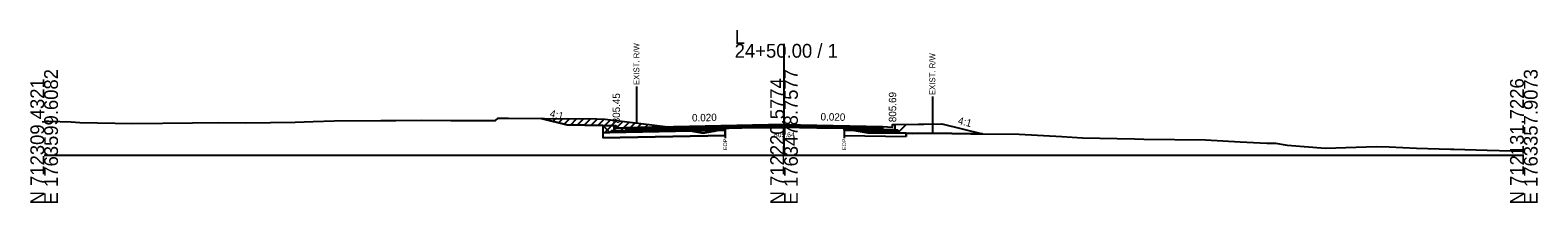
# Model space of a CAD drawing. Extents: x -26 to 5303, y -10 to 9578.
# Drawn here: x 997.2 to 1302.8, y 4490.3 to 4525.4 of the extents above; entities that cross this region are included whole.
import ezdxf

# ---------------------------------------------------------------- set-up
doc = ezdxf.new("R2010")
doc.units = 0
for name, color, linetype in [('Default', 7, 'Continuous'), ('Exist CMT Pavement', 7, 'Continuous'), ('Exist Cross Section Cell', 7, 'Continuous'), ('Exist XS Ground Line', 7, 'Continuous'), ('Old_Level_10', 7, 'Continuous'), ('Old_Level_3', 7, 'Continuous'), ('Prop CMT Conc Surface', 7, 'Continuous'), ('Prop CMT Concrete Structures', 7, 'Continuous'), ('Prop CMT Pvmt Course 1', 7, 'Continuous'), ('Prop CMT Pvmt Course 1 CG', 7, 'Continuous'), ('Prop CMT Pvmt Course 2', 7, 'Continuous'), ('Prop CMT Pvmt Course 3', 7, 'Continuous'), ('Prop CMT Pvmt Surface', 7, 'Continuous'), ('Prop CMT Slope Grass', 7, 'Continuous'), ('Prop CMT Subgrade Earthwork', 7, 'Continuous'), ('Prop Shade Light', 7, 'Continuous'), ('Prop XS Earthwork Shape', 7, 'Continuous'), ('Prop XS Hydro Elevations', 7, 'Continuous'), ('Prop XS SE Text', 7, 'Continuous'), ('Prop XS Side Slope Text', 7, 'Continuous'), ('Prop XS Wedging', 7, 'Continuous'), ('Scratch_Level_5', 7, 'Continuous')]:
    doc.layers.add(name, color=color, linetype=linetype)

msp = doc.modelspace()

# ---------------------------------------------------------------- linework, layer by layer
at = {"layer": 'Exist CMT Pavement'}
msp.add_lwpolyline([(1138.07, 4505.48), (1138.48, 4505.48), (1138.8, 4505.49), (1140.7, 4505.56), (1141.47, 4505.57), (1143.8, 4505.6), (1144.64, 4505.61), (1145.95, 4505.61), (1146.91, 4505.62), (1147.74, 4505.63), (1148.86, 4505.64), (1149.6, 4505.64), (1150.38, 4505.65), (1150.92, 4505.65), (1151.31, 4505.65), (1153.11, 4505.62), (1154.89, 4505.6), (1156.22, 4505.58), (1156.68, 4505.57), (1157.31, 4505.56), (1158.47, 4505.54), (1159.32, 4505.53), (1160.25, 4505.53), (1160.8, 4505.52), (1162.19, 4505.49), (1162.19, 4505.49)], dxfattribs=at)
at = {"layer": 'Exist Cross Section Cell'}
for p, q in [((1150, 4500), (1150, 4522.59)), ((1000, 4500), (1150, 4500)), ((1150, 4500), (1300, 4500))]:
    msp.add_line(p, q, dxfattribs=at)
at = {"layer": 'Exist XS Ground Line'}
msp.add_lwpolyline([(1000, 4506.88), (1000.93, 4506.88), (1005.5, 4506.75), (1007.2, 4506.64), (1018, 4506.42), (1030.09, 4506.57), (1035.26, 4506.66), (1040.86, 4506.57), (1050.89, 4506.71), (1054.53, 4506.82), (1058.77, 4506.97), (1068.24, 4507.04), (1070.32, 4507.04), (1071.28, 4507.05), (1076.57, 4507.1), (1082.46, 4507.05), (1090.03, 4507.06), (1091.53, 4507.02), (1092.03, 4507.53), (1094.12, 4507.48), (1101.42, 4507.45), (1112.08, 4507.38), (1113.73, 4507.3), (1123.77, 4506.08), (1126.87, 4505.68), (1133.64, 4504.43), (1135.87, 4504.86), (1138.07, 4505.48), (1138.48, 4505.48), (1138.8, 4505.49), (1140.7, 4505.56), (1142.37, 4505.58), (1143.8, 4505.6), (1144.16, 4505.61), (1144.64, 4505.61), (1145.95, 4505.61), (1146.91, 4505.62), (1147.74, 4505.63), (1148.86, 4505.64), (1149.6, 4505.64), (1150.38, 4505.65), (1150.92, 4505.65), (1151.31, 4505.65), (1153.19, 4505.62), (1156.22, 4505.58), (1156.68, 4505.57), (1157.31, 4505.56), (1158.47, 4505.54), (1159.32, 4505.53), (1160.25, 4505.53), (1160.8, 4505.52), (1162.19, 4505.49), (1163.45, 4505.16), (1167, 4504.54), (1173.14, 4504.56), (1175.96, 4504.41), (1180.15, 4504.49), (1187.88, 4504.33), (1197.69, 4504.29), (1206.33, 4503.76), (1210.55, 4503.53), (1221.07, 4503.28), (1222.98, 4503.24), (1235.46, 4503.12), (1242.5, 4502.7), (1247.87, 4502.44), (1249.65, 4502.4), (1252.02, 4502.06), (1259.79, 4501.45), (1270.14, 4501.74), (1272.7, 4501.67), (1278.27, 4501.42), (1285.11, 4501.22), (1285.42, 4501.21), (1285.84, 4501.2), (1292.58, 4501.03), (1297.53, 4500.9), (1300, 4500.89)], dxfattribs=at)
at = {"layer": 'Old_Level_10'}
for p, q in [((1120.08, 4513.93), (1120.08, 4506.52)), ((1180.08, 4511.89), (1180.08, 4504.49)), ((1138.07, 4505.48), (1138.07, 4503.43)), ((1162.19, 4505.49), (1162.19, 4503.44))]:
    msp.add_line(p, q, dxfattribs=at)
at = {"layer": 'Prop CMT Conc Surface'}
for points in [[(1116, 4505.45), (1116, 4505.95), (1115.5, 4505.95)], [(1170, 4505.81), (1172, 4505.69)], [(1172, 4505.69), (1172, 4506.19), (1172.5, 4506.19)], [(1118, 4505.57), (1116, 4505.45)]]:
    msp.add_lwpolyline(points, dxfattribs=at)
at = {"layer": 'Prop CMT Concrete Structures'}
for points in [[(1118, 4505.57), (1116, 4505.45), (1116, 4505.95), (1115.5, 4505.95)], [(1115.5, 4505.95), (1115.5, 4504.93), (1118, 4504.98)], [(1170, 4505.81), (1172, 4505.69), (1172, 4506.19), (1172.5, 4506.19)], [(1172.5, 4506.19), (1172.5, 4505.17), (1170, 4505.22)], [(1170, 4505.22), (1170, 4505.81)], [(1118, 4504.98), (1118, 4505.57)]]:
    msp.add_lwpolyline(points, dxfattribs=at)
at = {"layer": 'Prop CMT Pvmt Course 1'}
for points in [[(1150, 4506.21), (1118, 4505.57)], [(1138.07, 4505.72), (1150, 4505.96)], [(1150, 4505.96), (1150, 4506.21)], [(1150, 4506.21), (1170, 4505.81)], [(1150, 4505.96), (1150, 4505.96), (1150, 4505.96)], [(1162.19, 4505.71), (1150, 4505.96)], [(1170, 4505.81), (1170, 4505.56)], [(1118, 4505.32), (1138.07, 4505.72)], [(1118, 4505.57), (1118, 4505.32)], [(1138.07, 4505.72), (1138.07, 4505.72)], [(1170, 4505.56), (1162.19, 4505.71)], [(1162.19, 4505.71), (1162.19, 4505.71)]]:
    msp.add_lwpolyline(points, dxfattribs=at)
at = {"layer": 'Prop CMT Pvmt Course 1 CG'}
for points in [[(1118, 4504.98), (1115, 4504.92), (1114.66, 4504.58)], [(1114.66, 4504.58), (1118, 4504.65)], [(1118, 4504.65), (1118, 4504.98)], [(1170, 4505.22), (1173, 4505.16), (1173.34, 4504.82)], [(1170, 4504.89), (1170, 4505.22)], [(1173.34, 4504.82), (1170, 4504.89)]]:
    msp.add_lwpolyline(points, dxfattribs=at)
at = {"layer": 'Prop CMT Pvmt Course 2'}
for points in [[(1138.07, 4505.72), (1118, 4505.32)], [(1118, 4504.98), (1138.07, 4505.38)], [(1118, 4505.32), (1118, 4504.98)], [(1138.07, 4505.38), (1138.07, 4505.72)], [(1162.19, 4505.38), (1162.19, 4505.71)], [(1162.19, 4505.71), (1170, 4505.56)], [(1170, 4505.22), (1162.19, 4505.38)], [(1170, 4505.56), (1170, 4505.22)]]:
    msp.add_lwpolyline(points, dxfattribs=at)
at = {"layer": 'Prop CMT Pvmt Course 3'}
for points in [[(1138.07, 4505.38), (1118, 4504.98)], [(1118, 4504.65), (1138.07, 4505.05)], [(1118, 4504.98), (1118, 4504.65)], [(1138.07, 4505.05), (1138.07, 4505.38)], [(1162.19, 4505.38), (1170, 4505.22)], [(1162.19, 4505.05), (1162.19, 4505.38)], [(1170, 4504.89), (1162.19, 4505.05)], [(1170, 4505.22), (1170, 4504.89)]]:
    msp.add_lwpolyline(points, dxfattribs=at)
at = {"layer": 'Prop CMT Pvmt Surface'}
for points in [[(1150, 4506.21), (1118, 4505.57)], [(1150, 4506.21), (1170, 4505.81)]]:
    msp.add_lwpolyline(points, dxfattribs=at)
at = {"layer": 'Prop CMT Slope Grass'}
for points in [[(1115.5, 4505.95), (1106, 4506.14), (1100.74, 4507.45)], [(1172.5, 4506.19), (1182, 4506.38), (1190.22, 4504.32)]]:
    msp.add_lwpolyline(points, dxfattribs=at)
at = {"layer": 'Prop CMT Subgrade Earthwork'}
for p, q in [((1138.07, 4505.05), (1138.07, 4505.48)), ((1162.19, 4505.05), (1162.19, 4505.49))]:
    msp.add_line(p, q, dxfattribs=at)
for points in [[(1118, 4504.65), (1114.66, 4504.58), (1113.25, 4505.99)], [(1170, 4504.89), (1173.34, 4504.82), (1174.75, 4506.23)], [(1138.07, 4505.05), (1118, 4504.65)], [(1162.19, 4505.05), (1170, 4504.89)]]:
    msp.add_lwpolyline(points, dxfattribs=at)
at = {"layer": 'Prop Shade Light'}
for p, q in [((1113.25, 4504.55), (1114.66, 4504.58)), ((1114.66, 4504.58), (1113.25, 4504.55)), ((1113.25, 4504.55), (1113.25, 4503.52)), ((1113.25, 4504.55), (1113.25, 4503.52)), ((1113.25, 4503.52), (1138.07, 4504.01)), ((1118, 4504.65), (1114.66, 4504.58)), ((1131.05, 4504.91), (1118, 4504.65)), ((1138.07, 4505.05), (1136.43, 4505.02)), ((1138.07, 4505.05), (1138.07, 4504.01)), ((1138.07, 4504.01), (1138.07, 4505.05)), ((1162.19, 4505.05), (1162.19, 4504.01)), ((1162.19, 4505.05), (1162.19, 4504.01)), ((1165.11, 4504.99), (1162.19, 4505.05)), ((1162.19, 4504.01), (1174.75, 4503.76)), ((1174.75, 4504.47), (1174.75, 4503.76)), ((1174.75, 4503.76), (1174.75, 4504.47))]:
    msp.add_line(p, q, dxfattribs=at)
for points in [[(1138.07, 4504.01), (1113.25, 4503.52)], [(1136.43, 4505.02), (1135.87, 4504.86), (1133.64, 4504.43), (1131.05, 4504.91)], [(1162.19, 4504.01), (1174.75, 4503.76)], [(1174.75, 4504.47), (1173.14, 4504.56), (1167, 4504.54), (1165.11, 4504.99)]]:
    msp.add_lwpolyline(points, dxfattribs=at)
at = {"layer": 'Prop XS Earthwork Shape'}
for points in [[(1101.42, 4507.45), (1112.08, 4507.38), (1113.73, 4507.3), (1123.77, 4506.08), (1126.44, 4505.73), (1118, 4505.57), (1116, 4505.45), (1116, 4505.95), (1115.5, 4505.95), (1113.25, 4505.99), (1106, 4506.14), (1100.74, 4507.45)], [(1131.05, 4504.91), (1118, 4504.65), (1114.66, 4504.58), (1113.25, 4505.99), (1115.5, 4505.95), (1116, 4505.95), (1116, 4505.45), (1118, 4505.57), (1126.44, 4505.73), (1126.87, 4505.68)], [(1174.75, 4506.23), (1182, 4506.38), (1190.22, 4504.32), (1187.88, 4504.33), (1180.15, 4504.49), (1175.96, 4504.41), (1173.14, 4504.56), (1167, 4504.54), (1165.11, 4504.99), (1170, 4504.89), (1173.34, 4504.82)], [(1131.05, 4504.91), (1133.64, 4504.43), (1135.87, 4504.86), (1136.43, 4505.02)], [(1136.43, 4505.02), (1138.07, 4505.48), (1138.07, 4505.05)], [(1164.26, 4505.19), (1165.11, 4504.99), (1162.19, 4505.05), (1162.19, 4505.49)]]:
    msp.add_lwpolyline(points, close=True, dxfattribs=at)
at = {"layer": 'Prop XS Wedging'}
for points in [[(1138.07, 4505.48), (1138.07, 4505.72), (1138.48, 4505.73), (1138.8, 4505.73), (1140.7, 4505.77), (1141.47, 4505.79), (1143.8, 4505.83), (1144.64, 4505.85), (1145.95, 4505.87), (1146.91, 4505.89), (1147.74, 4505.91), (1148.87, 4505.93), (1149.6, 4505.95), (1150, 4505.96), (1150.38, 4505.95), (1150.92, 4505.94), (1151.31, 4505.93), (1153.11, 4505.89), (1154.89, 4505.86), (1156.22, 4505.83), (1156.68, 4505.82), (1157.31, 4505.81), (1158.47, 4505.79), (1159.32, 4505.77), (1160.25, 4505.75), (1160.8, 4505.74), (1162.19, 4505.71), (1162.19, 4505.49), (1160.8, 4505.52), (1160.25, 4505.53), (1159.32, 4505.53), (1158.47, 4505.54), (1157.31, 4505.56), (1156.68, 4505.57), (1156.22, 4505.58), (1154.89, 4505.6), (1153.11, 4505.62), (1151.31, 4505.65), (1150.92, 4505.65), (1150.38, 4505.65), (1150, 4505.64), (1149.6, 4505.64), (1148.87, 4505.64), (1147.74, 4505.63), (1146.91, 4505.62), (1145.95, 4505.61), (1144.64, 4505.61), (1143.8, 4505.6), (1141.47, 4505.57), (1140.7, 4505.57), (1138.8, 4505.49), (1138.48, 4505.48)], [(1138.07, 4505.48), (1138.07, 4505.72), (1138.48, 4505.73), (1138.8, 4505.73), (1140.54, 4505.77), (1140.74, 4505.57), (1138.8, 4505.49), (1138.48, 4505.48)], [(1140.96, 4505.57), (1141.18, 4505.78), (1141.47, 4505.79), (1143.8, 4505.83), (1144.64, 4505.85), (1145.95, 4505.87), (1146.91, 4505.89), (1147.74, 4505.91), (1148.87, 4505.93), (1149.6, 4505.95), (1150, 4505.96), (1150.38, 4505.95), (1150.92, 4505.94), (1151.31, 4505.93), (1153.11, 4505.89), (1154.89, 4505.86), (1156.22, 4505.83), (1156.68, 4505.82), (1157.31, 4505.81), (1158.47, 4505.79), (1159.32, 4505.77), (1160.25, 4505.75), (1160.8, 4505.74), (1162.19, 4505.71), (1162.19, 4505.49), (1160.8, 4505.52), (1160.25, 4505.53), (1159.32, 4505.53), (1158.47, 4505.54), (1157.31, 4505.56), (1156.68, 4505.57), (1156.22, 4505.58), (1154.89, 4505.6), (1153.11, 4505.62), (1151.31, 4505.65), (1150.92, 4505.65), (1150.38, 4505.65), (1150, 4505.64), (1149.6, 4505.64), (1148.87, 4505.64), (1147.74, 4505.63), (1146.91, 4505.62), (1145.95, 4505.61), (1144.64, 4505.61), (1143.8, 4505.6), (1141.47, 4505.57)]]:
    msp.add_lwpolyline(points, close=True, dxfattribs=at)
at = {"layer": 'Scratch_Level_5'}
for p, q in [((1100.74, 4507.45), (1106, 4506.14)), ((1100.9, 4507.41), (1100.94, 4507.45)), ((1102.03, 4507.13), (1102.34, 4507.44)), ((1103.16, 4506.84), (1103.75, 4507.43)), ((1104.29, 4506.56), (1105.16, 4507.43)), ((1105.42, 4506.28), (1106.56, 4507.42)), ((1106, 4506.14), (1113.25, 4505.99)), ((1106.68, 4506.12), (1107.97, 4507.41)), ((1108.07, 4506.09), (1109.37, 4507.4)), ((1109.45, 4506.07), (1110.78, 4507.39)), ((1110.84, 4506.04), (1112.18, 4507.38)), ((1112.23, 4506.01), (1113.52, 4507.31)), ((1113.25, 4505.62), (1114.8, 4507.17)), ((1113.25, 4505.99), (1113.25, 4504.55)), ((1113.61, 4504.56), (1116.06, 4507.01)), ((1115.05, 4504.59), (1117.32, 4506.86)), ((1116.49, 4504.62), (1118.58, 4506.71)), ((1117.93, 4504.65), (1119.84, 4506.55)), ((1119.38, 4504.68), (1121.1, 4506.4)), ((1120.82, 4504.71), (1122.36, 4506.25)), ((1122.26, 4504.73), (1123.62, 4506.09)), ((1123.71, 4504.76), (1124.88, 4505.93)), ((1125.15, 4504.79), (1126.13, 4505.77)), ((1126.59, 4504.82), (1127.36, 4505.59)), ((1128.04, 4504.85), (1128.56, 4505.37)), ((1129.48, 4504.88), (1129.75, 4505.15)), ((1130.92, 4504.91), (1130.94, 4504.93)), ((1137.64, 4505.04), (1138.07, 4505.47)), ((1162.19, 4505.49), (1162.19, 4505.05)), ((1162.19, 4505.08), (1162.56, 4505.44)), ((1163.55, 4505.02), (1163.79, 4505.26)), ((1164.93, 4504.99), (1164.97, 4505.02))]:
    msp.add_line(p, q, dxfattribs=at)

# ---------------------------------------------------------------- texts
at = {"layer": 'Default'}
msp.add_text('-', height=0.0001, dxfattribs=at).set_placement((1000, 4500))
at = {"layer": 'Exist Cross Section Cell'}
for s, p in [('L', (1140, 4522.59)), ('24+50.00 / 1', (1140, 4519.79))]:
    msp.add_text(s, height=2.8, dxfattribs=at).set_placement(p)
for s, p in [('N 712309.4321', (1000, 4490)), ('E 1763599.6082', (1002.8, 4490)), ('N 712220.5774', (1150, 4490)), ('E 1763478.7577', (1152.8, 4490)), ('N 712131.7226', (1300, 4490)), ('E 1763357.9073', (1302.8, 4490))]:
    msp.add_text(s, height=2.8, rotation=90, dxfattribs=at).set_placement(p)
at = {"layer": 'Old_Level_10'}
for s, height, p in [('EXIST. R/W', 1.181, (1120.67, 4514.23)), ('EXIST. R/W', 1.181, (1180.67, 4512.19)), ('EOP', 0.787, (1138.46, 4501.03)), ('EOP', 0.787, (1162.59, 4501.05))]:
    msp.add_text(s, height=height, rotation=90, dxfattribs=at).set_placement(p)
at = {"layer": 'Old_Level_3'}
msp.add_text('805.64', height=1, dxfattribs=at).set_placement((1147.95, 4503.64))
at = {"layer": 'Prop XS Hydro Elevations'}
for s, p in [('805.45', (1116.75, 4506.45)), ('805.69', (1172.75, 4506.69))]:
    msp.add_text(s, height=1.5, rotation=90, dxfattribs=at).set_placement(p)
at = {"layer": 'Prop XS SE Text'}
for rotation, p in [(1.1458, (1131.36, 4506.83)), (358.8542, (1157.4, 4507.06))]:
    msp.add_text('0.020', height=1.5, rotation=rotation, dxfattribs=at).set_placement(p)
at = {"layer": 'Prop XS Side Slope Text'}
for p in [(1102.4, 4507.81), (1185.14, 4506.36)]:
    msp.add_text('4:1', height=1.5, rotation=345.9638, dxfattribs=at).set_placement(p)

doc.saveas('drawing.dxf')
